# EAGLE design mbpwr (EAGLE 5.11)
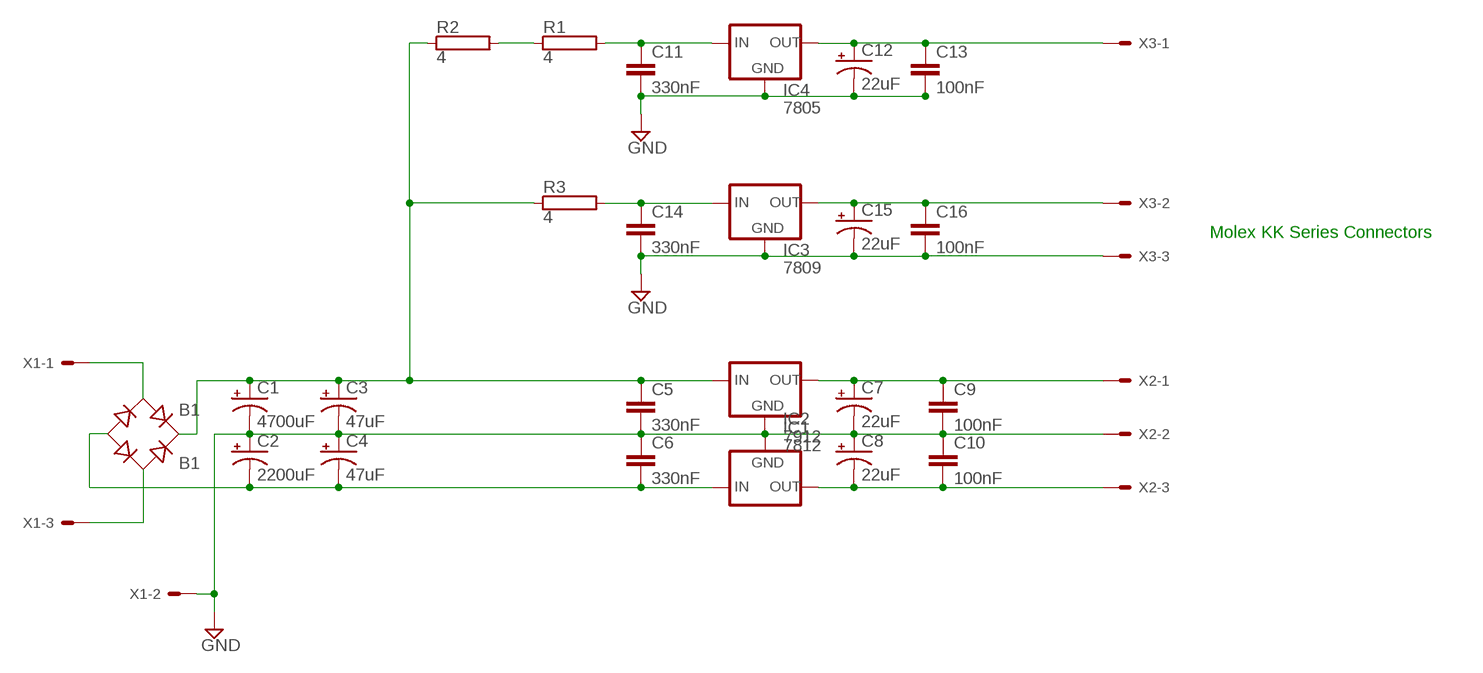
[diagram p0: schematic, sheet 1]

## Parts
B1  B1  RB1A  [RB1A]
C1  4700uF  CPOL-USE7.5-18  [E7,5-18]
C2  2200uF  CPOL-USE7.5-16  [E7,5-16]
C3  47uF  CPOL-USE2.5-5  [E2,5-5]
C4  47uF  CPOL-USE2.5-5  [E2,5-5]
C5  330nF  C-EU025-025X050  [C025-025X050]
C6  330nF  C-EU025-025X050  [C025-025X050]
C7  22uF  CPOL-USE2-5  [E2-5]
C8  22uF  CPOL-USE2-5  [E2-5]
C9  100nF  C-EU025-025X050  [C025-025X050]
C10  100nF  C-EU025-025X050  [C025-025X050]
C11  330nF  C-EU025-025X050  [C025-025X050]
C12  22uF  CPOL-USE2-5  [E2-5]
C13  100nF  C-EU025-025X050  [C025-025X050]
C14  330nF  C-EU025-025X050  [C025-025X050]
C15  22uF  CPOL-USE2-5  [E2-5]
C16  100nF  C-EU025-025X050  [C025-025X050]
IC1  7812  78XXS  [78XXS]
IC2  7912  79XXS  [79XXS]
IC3  7809  78XXS  [78XXS]
IC4  7805  78XXS  [78XXS]
R1  4  RKH206-8  [KH206-8]
R2  4  RKH206-8  [KH206-8]
R3  4  RKH206-8  [KH206-8]
X1  KK-156-3  [KK-156-3]
X2  KK-156-3  [KK-156-3]
X3  KK-156-3  [KK-156-3]

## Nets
+5VDC: C12.+ C13.1 IC4.OUT X3.1
+9VDC: C15.+ C16.1 IC3.OUT X3.2
+12VDC: C7.+ C9.1 IC1.OUT X2.1
+12VDC_UNREG: B1.+ C1.+ C3.+ C5.1 IC1.IN R2.1 R3.1
-12VDC: C8.- C10.2 IC2.OUT X2.3
-12VDC_UNREG: B1.- C2.- C4.- C6.2 IC2.IN
GND: C1.- C2.+ C3.- C4.+ C5.2 C6.1 C7.- C8.+ C9.2 C10.1 C11.2 C12.- C13.2 C14.2 C15.- C16.2 IC1.GND IC2.GND IC3.GND IC4.GND X1.2 X2.2 X3.3
N$1: C11.1 IC4.IN R1.2
N$2: C14.1 IC3.IN R3.2
N$3: R1.1 R2.2
N$5: B1.AC1 X1.1
N$6: B1.AC2 X1.3

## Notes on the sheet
- Molex KK Series Connectors

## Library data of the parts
B1 = rectifier:RB1A: RECTIFIER 1 A
C1 C2 C7 C8 C12 C15 = rcl:CPOL-US: POLARIZED CAPACITOR, American symbol
C3 C4 = resistor:CPOL-US: POLARIZED CAPACITOR, American symbol
C5 C6 C9-C11 C13 C14 C16 = rcl:C-EU: CAPACITOR, European symbol
IC1 IC3 IC4 = v-reg:78XXS: VOLTAGE REGULATOR
IC2 = v-reg:79XXS: VOLTAGE REGULATOR
R1-R3 = resistor-power:R: Power Resitor
X1-X3 = con-molex:KK-156-3: KK 156 HEADER Source: http://www.molex.com/pdm_docs/sd/026604100_sd.pdf; OC_FARNELL: unknown; OC_NEWARK: unknown

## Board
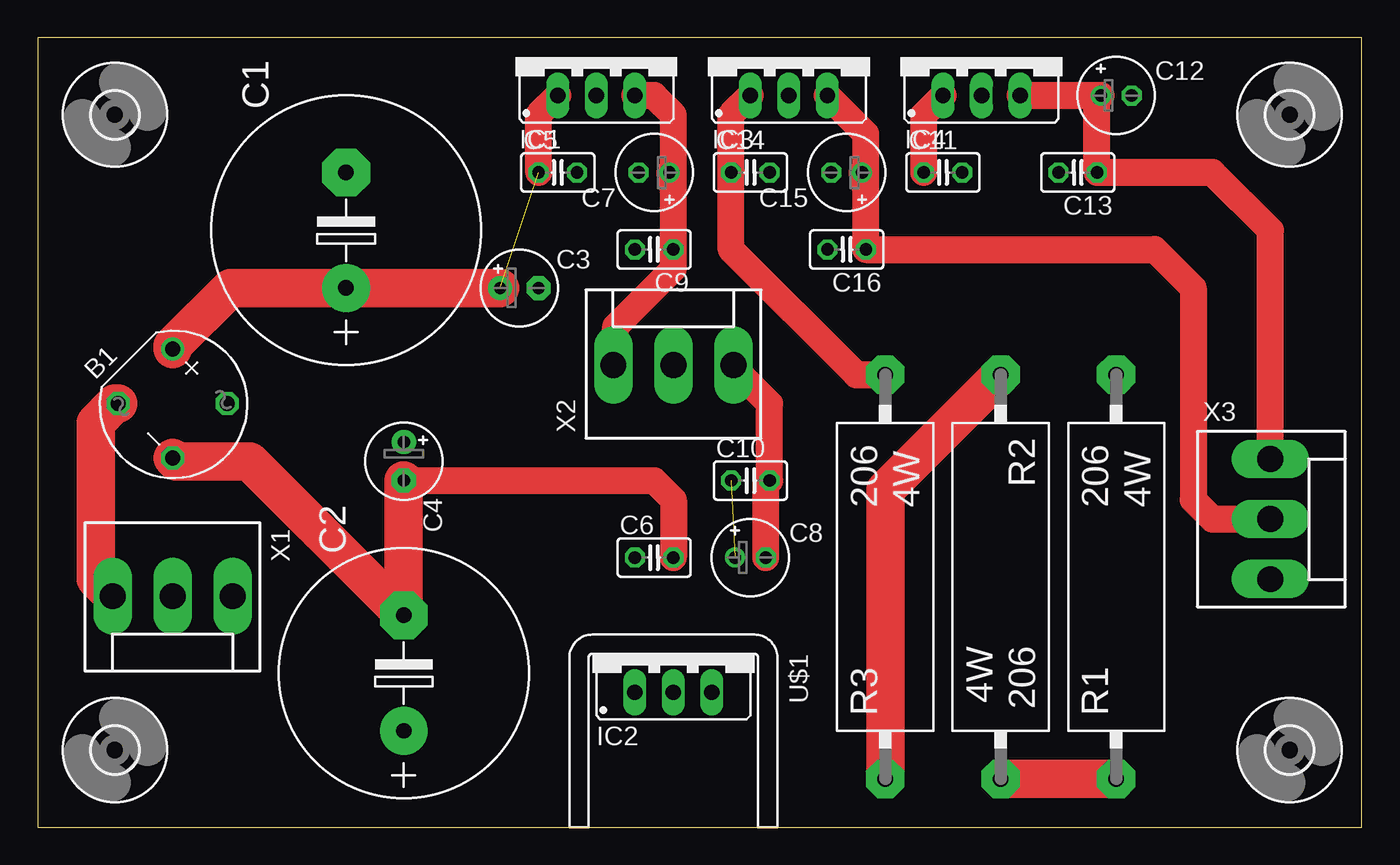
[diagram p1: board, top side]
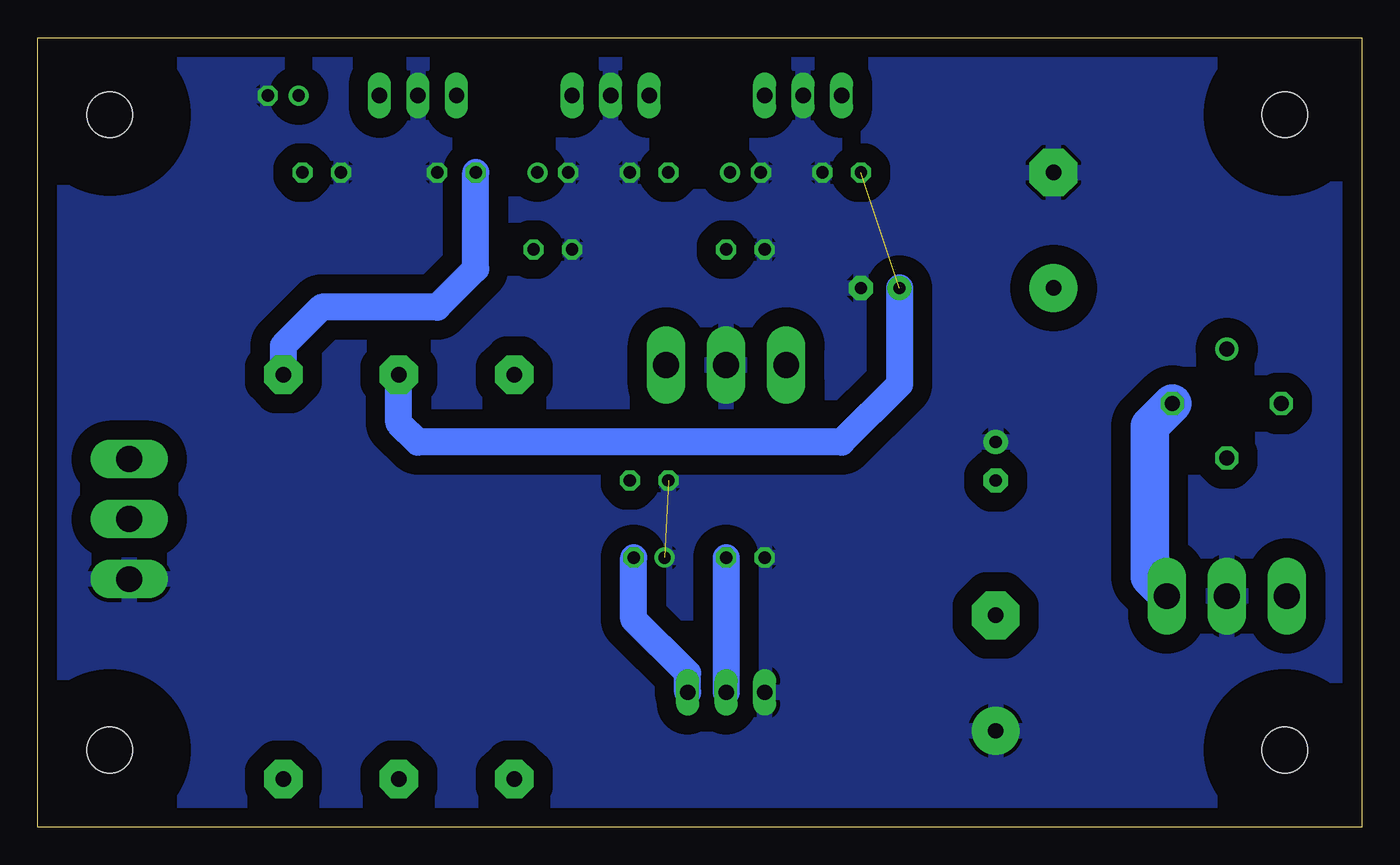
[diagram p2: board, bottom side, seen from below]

Size 87.3 x 52.06 mm. Coordinates in mm from the lower left corner, seen from the top.
Outline: 0,0 87.3,0 87.3,52.06 0,52.06 0,0
Copper layers (1*16): Top 0.035mm / dielectric 1.5mm / Bottom 0.035mm
Design rules "default": minimum track width 10mil, minimum drill 24mil, track to track 8mil, track to pad 8mil, pad to pad 8mil, via to via 8mil, smd to smd 8mil, copper to edge 40mil, drill to drill 8mil, minimum pad ring 10mil, minimum via ring 8mil, stop-mask expansion 4mil, vias tented up to drill 0mil, thermal gap 10mil

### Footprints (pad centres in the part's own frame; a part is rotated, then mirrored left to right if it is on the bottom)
RB1A = drill 1.016 round: + -2.54,2.54 | drill 1.016 octagon: - 2.54,-2.54; AC1 2.54,2.54; AC2 -2.54,-2.54
E7,5-18 = drill 1.016 pad 3.15 round: + -3.81,0 | drill 1.016 pad 3.15 octagon: - 3.81,0
E7,5-16 = drill 1.016 pad 3.15 round: + -3.81,0 | drill 1.016 pad 3.15 octagon: - 3.81,0
E2,5-5 = drill 0.813 pad 1.6 round: + -1.27,0 | drill 0.813 pad 1.6 octagon: - 1.27,0
C025-025X050 = drill 0.813 octagon: 1 -1.27,0; 2 1.27,0
E2-5 = drill 0.813 pad 1.27 round: + -1.016,0 | drill 0.813 pad 1.27 octagon: - 1.016,0
78XXS = drill 1.016 long: GND 0,-2.54; IN -2.54,-2.54; OUT 2.54,-2.54
79XXS = drill 1.016 long: GND -2.54,-2.54; IN 0,-2.54; OUT 2.54,-2.54
KH206-8 = drill 1.016 pad 2.54 octagon: 1 -13.335,0; 2 13.335,0
3,0 = hole 3: 0,0
KK-156-3 = drill 1.7 pad 2.184 long: 1 -3.96,0; 2 0,0; 3 3.96,0

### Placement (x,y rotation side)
B1  8.89,27.94 315 top
C1  20.32,39.37 90 top
C2  24.13,10.16 90 top
C3  31.75,35.56 0 top
C4  24.13,24.13 270 top
C5  34.29,43.18 0 top
C6  40.64,17.78 0 top
C7  40.64,43.18 180 top
C8  46.99,17.78 0 top
C9  40.64,38.1 180 top
C10  46.99,22.86 0 top
C11  59.69,43.18 0 top
C12  71.12,48.26 0 top
C13  68.58,43.18 180 top
C14  46.99,43.18 0 top
C15  53.34,43.18 180 top
C16  53.34,38.1 180 top
IC1  36.83,50.8 0 top
IC2  41.91,11.43 0 top
IC3  49.53,50.8 0 top
IC4  62.23,50.8 0 top
R1  71.12,16.51 90 top
R2  63.5,16.51 270 top
R3  55.88,16.51 90 top
U$1  [D01S]  41.91,11.43 180 top
U$2  [3,0]  5.08,5.08 0 top
U$3  [3,0]  5.08,46.99 0 top
U$4  [3,0]  82.55,46.99 0 top
U$5  [3,0]  82.55,5.08 0 top
X1  8.89,15.24 180 top
X2  41.91,30.48 0 top
X3  81.28,20.32 270 top

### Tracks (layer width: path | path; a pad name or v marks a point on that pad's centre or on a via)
+5VDC
  Top 1.778: IC4.OUT C12.+ 69.85,48.01 C13.1 77.47,43.18 81.28,39.37 X3.1
+9VDC
  Top 1.778: 54.61,41.91 C16.1 73.66,38.1 76.2,35.56 76.2,21.59 77.47,20.32 X3.2 | 54.61,41.91 54.61,45.72 IC3.OUT | 54.61,41.91 C15.+
+12VDC
  Top 1.778: IC1.OUT 40.64,48.26 41.91,46.99 41.91,41.91 | 41.91,41.91 C9.1 41.91,36.83 38.1,33.02 38.1,30.63 X2.1 | 41.91,41.91 C7.+
+12VDC_UNREG  (1 unrouted)
  Top 1.778: IC1.IN 33.02,46.99 C5.1
  Top 2.54: B1.+ 8.89,31.75 12.7,35.56 C1.+ C3.+ | R3.1 55.88,22.23 R2.1
  Bottom 1.778: R2.1 63.5,26.67 62.23,25.4 34.29,25.4 30.48,29.21 C3.+
-12VDC
  Top 1.778: X2.3 45.87,30.33 48.26,27.94 C10.2 48.01,22.61 C8.-
  Bottom 1.778: IC2.OUT 44.45,10.16 48.01,13.72 C8.-
-12VDC_UNREG
  Top 1.778: C6.2 41.91,21.59 40.64,22.86 C4.-
  Top 2.54: B1.- 9.11,24.13 13.97,24.13 C2.- C4.-
  Bottom 1.778: C6.2 IC2.IN
GND  (1 unrouted)
  pour Bottom (isolate 1.27): 0,52.07 87.63,52.07 87.63,0 0,0
N$1
  Top 1.778: C11.1 58.42,46.99 IC4.IN
  Bottom 1.778: C11.1 58.42,36.83 60.96,34.29 68.58,34.29 71.12,31.75 R1.2
N$2
  Top 1.778: IC3.IN 45.72,46.99 C14.1 45.72,38.1 53.98,29.84 R3.2
N$3
  Top 2.54: R2.2 R1.1
N$5
  Bottom 2.54: X1.1 12.85,15.39 13.97,16.51 13.97,26.45 B1.AC1
N$6
  Top 2.54: B1.AC2 5.08,27.94 3.81,26.67 3.81,16.36 X1.3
